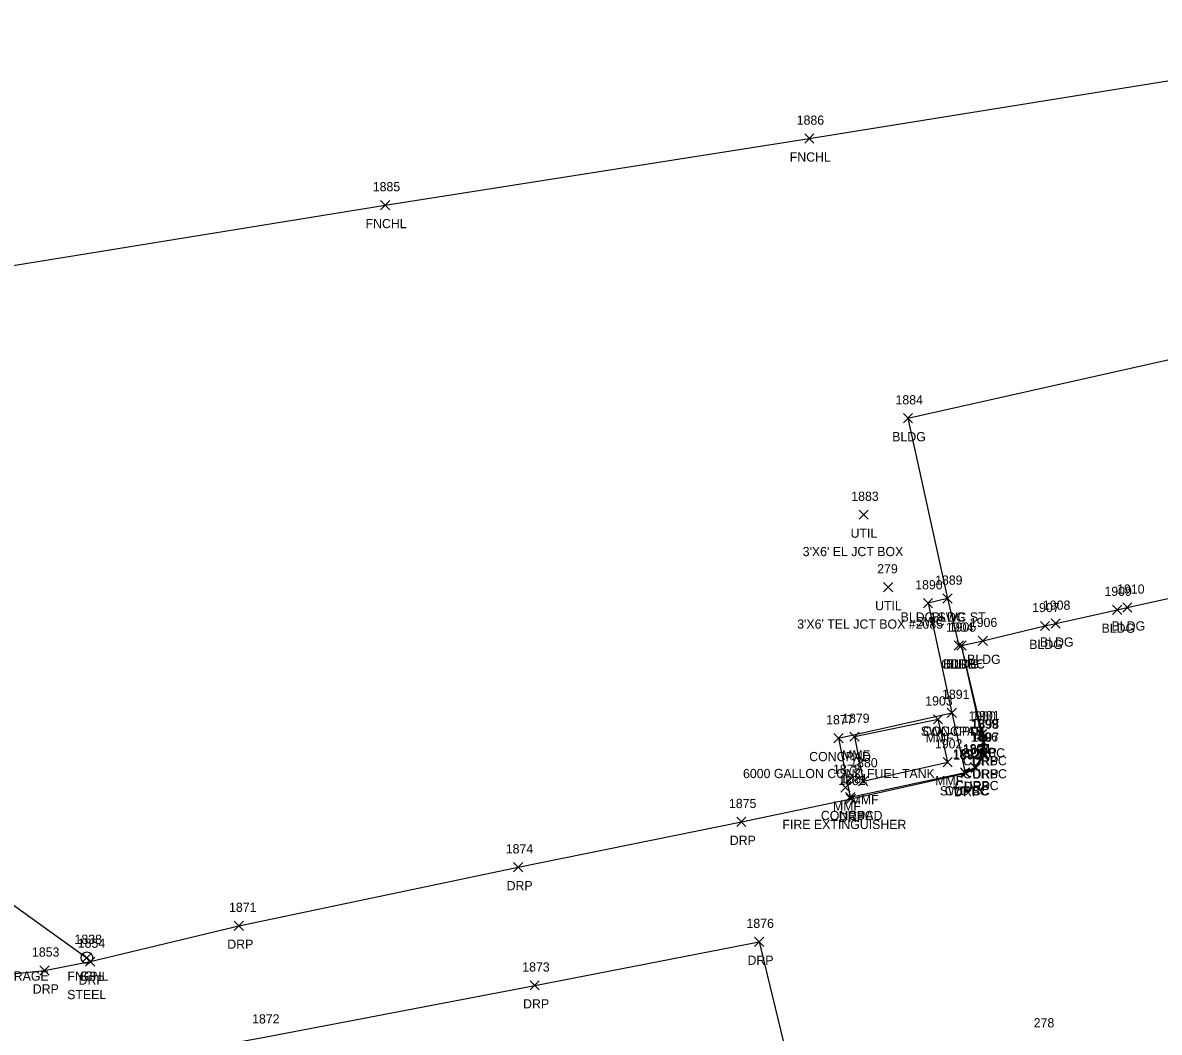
# Model space of a CAD drawing. Extents: x 1481523 to 1489083, y 884156 to 893756.
# Drawn here: x 1486651.1 to 1486897.7, y 888454.5 to 888673.5 of the extents above; entities that cross this region are included whole.
import ezdxf

# ---------------------------------------------------------------- set-up
doc = ezdxf.new("R2010")
doc.units = 0
for name, color, linetype in [('C_I', 7, 'Continuous'), ('L_A', 7, 'Continuous'), ('L_C', 7, 'Continuous'), ('L_I', 7, 'Continuous'), ('L_TIC', 7, 'Continuous'), ('LBC', 7, 'Continuous'), ('LDEFAULT', 7, 'Continuous'), ('LFNC', 7, 'Continuous'), ('LS', 7, 'Continuous'), ('R_A', 7, 'Continuous'), ('R_C', 7, 'Continuous'), ('R_I', 7, 'Continuous'), ('R_TIC', 7, 'Continuous'), ('RC', 7, 'Continuous'), ('RDP', 7, 'Continuous'), ('RGP', 7, 'Continuous'), ('RSW', 7, 'Continuous'), ('S_C', 7, 'Continuous'), ('U_A', 7, 'Continuous'), ('U_C', 7, 'Continuous'), ('U_I', 7, 'Continuous'), ('UDEFAULT', 7, 'Continuous')]:
    doc.layers.add(name, color=color, linetype=linetype)

msp = doc.modelspace()

# ---------------------------------------------------------------- linework, layer by layer
at = {"layer": 'L_TIC'}
for points in [[(1486820.77, 888647.41), (1486822.77, 888649.41)], [(1486822.77, 888647.41), (1486820.77, 888649.41)], [(1486728.72, 888632.96), (1486730.72, 888634.96)], [(1486730.72, 888632.96), (1486728.72, 888634.96)], [(1486842.17, 888586.71), (1486844.17, 888588.71)], [(1486844.17, 888586.71), (1486842.17, 888588.71)], [(1486842.17, 888586.71), (1486844.17, 888588.71)], [(1486844.17, 888586.71), (1486842.17, 888588.71)], [(1486850.76, 888547.58), (1486852.76, 888549.58)], [(1486852.76, 888547.58), (1486850.76, 888549.58)], [(1486887.59, 888545.15), (1486889.59, 888547.15)], [(1486889.59, 888545.15), (1486887.59, 888547.15)], [(1486889.77, 888545.64), (1486891.77, 888547.64)], [(1486891.77, 888545.64), (1486889.77, 888547.64)], [(1486874.23, 888542.15), (1486876.23, 888544.15)], [(1486876.23, 888542.15), (1486874.23, 888544.15)], [(1486871.9, 888541.63), (1486873.9, 888543.63)], [(1486873.9, 888541.63), (1486871.9, 888543.63)], [(1486853.19, 888537.38), (1486855.19, 888539.38)], [(1486855.19, 888537.38), (1486853.19, 888539.38)], [(1486853.8, 888537.4), (1486855.8, 888539.4)], [(1486855.8, 888537.4), (1486853.8, 888539.4)], [(1486858.42, 888538.39), (1486860.42, 888540.39)], [(1486860.42, 888538.39), (1486858.42, 888540.39)], [(1486851.69, 888522.8), (1486853.69, 888524.8)], [(1486853.69, 888522.8), (1486851.69, 888524.8)], [(1486848.7, 888521.37), (1486850.7, 888523.37)], [(1486850.7, 888521.37), (1486848.7, 888523.37)], [(1486848.7, 888521.37), (1486850.7, 888523.37)], [(1486850.7, 888521.37), (1486848.7, 888523.37)], [(1486827.1, 888517.29), (1486829.1, 888519.29)], [(1486829.1, 888517.29), (1486827.1, 888519.29)], [(1486827.1, 888517.29), (1486829.1, 888519.29)], [(1486829.1, 888517.29), (1486827.1, 888519.29)], [(1486830.59, 888517.61), (1486832.59, 888519.61)], [(1486832.59, 888517.61), (1486830.59, 888519.61)], [(1486830.59, 888517.61), (1486832.59, 888519.61)], [(1486832.59, 888517.61), (1486830.59, 888519.61)], [(1486850.79, 888512.06), (1486852.79, 888514.06)], [(1486852.79, 888512.06), (1486850.79, 888514.06)], [(1486832.43, 888507.95), (1486834.43, 888509.95)], [(1486834.43, 888507.95), (1486832.43, 888509.95)], [(1486828.6, 888506.56), (1486830.6, 888508.56)], [(1486830.6, 888506.56), (1486828.6, 888508.56)], [(1486829.63, 888504.5), (1486831.63, 888506.5)], [(1486831.63, 888504.5), (1486829.63, 888506.5)], [(1486664.01, 888469.64), (1486666.01, 888471.64)], [(1486666.01, 888469.64), (1486664.01, 888471.64)]]:
    msp.add_lwpolyline(points, dxfattribs=at)
at = {"layer": 'LBC'}
for points in [[(1486843.17, 888587.71), (1487025.25, 888628.62)], [(1486843.17, 888587.71), (1486851.76, 888548.58), (1486854.19, 888538.38), (1486854.8, 888538.4), (1486859.42, 888539.39), (1486872.9, 888542.63), (1486875.23, 888543.15), (1486888.59, 888546.15), (1486890.77, 888546.64), (1486904.16, 888549.62)]]:
    msp.add_lwpolyline(points, dxfattribs=at)
at = {"layer": 'LDEFAULT'}
for points in [[(1486831.59, 888518.61), (1486833.43, 888508.95), (1486851.79, 888513.06), (1486849.7, 888522.37)], [(1486831.59, 888518.61), (1486849.7, 888522.37)]]:
    msp.add_lwpolyline(points, dxfattribs=at)
at = {"layer": 'LFNC'}
for points in [[(1486611.93, 888614.86), (1486729.72, 888633.96), (1486821.77, 888648.41), (1486910.35, 888662.67), (1486965.56, 888671.42), (1487049.78, 888685.11)], [(1486611.93, 888614.86), (1486623.3, 888550.21), (1486633.47, 888493.25), (1486665.01, 888470.64)]]:
    msp.add_lwpolyline(points, dxfattribs=at)
at = {"layer": 'LS'}
for points in [[(1486828.1, 888518.29), (1486852.69, 888523.8)], [(1486828.1, 888518.29), (1486830.63, 888505.5)]]:
    msp.add_lwpolyline(points, dxfattribs=at)
at = {"layer": 'R_TIC'}
for points in [[(1486850.76, 888547.58), (1486852.76, 888549.58)], [(1486852.76, 888547.58), (1486850.76, 888549.58)], [(1486846.53, 888546.57), (1486848.53, 888548.57)], [(1486848.53, 888546.57), (1486846.53, 888548.57)], [(1486853.8, 888537.4), (1486855.8, 888539.4)], [(1486855.8, 888537.4), (1486853.8, 888539.4)], [(1486853.8, 888537.4), (1486855.8, 888539.4)], [(1486855.8, 888537.4), (1486853.8, 888539.4)], [(1486851.69, 888522.8), (1486853.69, 888524.8)], [(1486853.69, 888522.8), (1486851.69, 888524.8)], [(1486858.15, 888518.09), (1486860.15, 888520.09)], [(1486860.15, 888518.09), (1486858.15, 888520.09)], [(1486858.32, 888518.19), (1486860.32, 888520.19)], [(1486860.32, 888518.19), (1486858.32, 888520.19)], [(1486858.52, 888516.39), (1486860.52, 888518.39)], [(1486860.52, 888516.39), (1486858.52, 888518.39)], [(1486858.68, 888516.32), (1486860.68, 888518.32)], [(1486860.68, 888516.32), (1486858.68, 888518.32)], [(1486858.53, 888513.55), (1486860.53, 888515.55)], [(1486860.53, 888513.55), (1486858.53, 888515.55)], [(1486858.69, 888513.5), (1486860.69, 888515.5)], [(1486860.69, 888513.5), (1486858.69, 888515.5)], [(1486854.56, 888509.86), (1486856.56, 888511.86)], [(1486856.56, 888509.86), (1486854.56, 888511.86)], [(1486854.56, 888509.86), (1486856.56, 888511.86)], [(1486856.56, 888509.86), (1486854.56, 888511.86)], [(1486856.75, 888511), (1486858.75, 888513)], [(1486858.75, 888511), (1486856.75, 888513)], [(1486856.86, 888510.81), (1486858.86, 888512.81)], [(1486858.86, 888510.81), (1486856.86, 888512.81)], [(1486854.7, 888509.65), (1486856.7, 888511.65)], [(1486856.7, 888509.65), (1486854.7, 888511.65)], [(1486829.63, 888504.5), (1486831.63, 888506.5)], [(1486831.63, 888504.5), (1486829.63, 888506.5)], [(1486829.76, 888504.1), (1486831.76, 888506.1)], [(1486831.76, 888504.1), (1486829.76, 888506.1)], [(1486806.02, 888499.11), (1486808.02, 888501.11)], [(1486808.02, 888499.11), (1486806.02, 888501.11)], [(1486757.59, 888489.27), (1486759.59, 888491.27)], [(1486759.59, 888489.27), (1486757.59, 888491.27)], [(1486696.98, 888476.57), (1486698.98, 888478.57)], [(1486698.98, 888476.57), (1486696.98, 888478.57)], [(1486809.87, 888473.09), (1486811.87, 888475.09)], [(1486811.87, 888473.09), (1486809.87, 888475.09)], [(1486664.71, 888468.79), (1486666.71, 888470.79)], [(1486666.71, 888468.79), (1486664.71, 888470.79)], [(1486654.78, 888466.86), (1486656.78, 888468.86)], [(1486656.78, 888466.86), (1486654.78, 888468.86)], [(1486761.17, 888463.63), (1486763.17, 888465.63)], [(1486763.17, 888463.63), (1486761.17, 888465.63)]]:
    msp.add_lwpolyline(points, dxfattribs=at)
at = {"layer": 'RC'}
msp.add_lwpolyline([(1486830.63, 888505.5), (1486855.56, 888510.86), (1486857.75, 888512), (1486859.53, 888514.55), (1486859.52, 888517.39), (1486859.15, 888519.09), (1486854.8, 888538.4)], dxfattribs=at)
at = {"layer": 'RDP'}
for points in [[(1486614.23, 888481.5), (1486627.34, 888469.66), (1486637.68, 888466), (1486655.78, 888467.86), (1486665.71, 888469.79), (1486697.98, 888477.57), (1486758.59, 888490.27), (1486807.02, 888500.11), (1486830.76, 888505.1), (1486855.7, 888510.65), (1486857.86, 888511.81), (1486859.69, 888514.5), (1486859.68, 888517.32), (1486859.32, 888519.19), (1486854.8, 888538.4)], [(1486627.06, 888409.28), (1486634.2, 888424.78), (1486643.14, 888435.44), (1486660.74, 888444.3), (1486670.7, 888447.41), (1486703.54, 888453.36), (1486762.17, 888464.63), (1486810.87, 888474.09), (1486835.34, 888373.21), (1486845.25, 888329.26)]]:
    msp.add_lwpolyline(points, dxfattribs=at)
at = {"layer": 'RGP'}
msp.add_line((1486665.01, 888470.64), (1486665.01, 888470.64), dxfattribs=at)
for radius in [1.25, 0.0833]:
    msp.add_circle((1486665.01, 888470.64), radius, dxfattribs=at)
at = {"layer": 'RSW'}
msp.add_lwpolyline([(1486851.76, 888548.58), (1486847.53, 888547.57), (1486852.69, 888523.8), (1486855.56, 888510.86)], dxfattribs=at)
at = {"layer": 'UDEFAULT'}
for points in [[(1486832.56, 888565.78), (1486834.56, 888567.78)], [(1486834.56, 888565.78), (1486832.56, 888567.78)], [(1486837.87, 888550.04), (1486839.87, 888552.04)], [(1486839.87, 888550.04), (1486837.87, 888552.04)]]:
    msp.add_lwpolyline(points, dxfattribs=at)

# ---------------------------------------------------------------- texts
at = {"layer": 'C_I'}
msp.add_text('278', height=2, dxfattribs=at).set_placement((1486870.46, 888455.51))
at = {"layer": 'L_A'}
for s, p in [('FNCHL', (1486817.52, 888643.41)), ('FNCHL', (1486725.47, 888628.96)), ('BLDG', (1486839.76, 888582.71)), ('BLDG', (1486839.76, 888582.71)), ('BLDG', (1486848.35, 888543.58)), ('BLDG', (1486885.18, 888541.15)), ('BLDG', (1486887.36, 888541.64)), ('BLDG', (1486869.49, 888537.63)), ('BLDG', (1486871.82, 888538.15)), ('BLDG', (1486850.78, 888533.38)), ('BLDG', (1486851.39, 888533.4)), ('BLDG', (1486856.01, 888534.39)), ('CONCPAD', (1486846.34, 888518.8)), ('MMF', (1486846.98, 888517.37)), ('MMF', (1486846.98, 888517.37)), ('CONCPAD', (1486821.75, 888513.29)), ('CONCPAD', (1486821.75, 888513.29)), ('MMF', (1486828.87, 888513.61)), ('MMF', (1486828.87, 888513.61)), ('MMF', (1486849.08, 888508.06)), ('MMF', (1486826.89, 888502.56)), ('MMF', (1486830.72, 888503.95)), ('CONCPAD', (1486824.27, 888500.5)), ('FNCHL', (1486660.76, 888465.64))]:
    msp.add_text(s, height=2, dxfattribs=at).set_placement(p)
at = {"layer": 'L_C'}
for s, p in [('6000 GALLON CONC FUEL TANK', (1486807.38, 888509.61)), ('6000 GALLON CONC FUEL TANK', (1486807.38, 888509.61)), ('FIRE EXTINGUISHER', (1486815.93, 888498.56))]:
    msp.add_text(s, height=2, dxfattribs=at).set_placement(p)
at = {"layer": 'L_I'}
for s, p in [('1886', (1486819.03, 888651.41)), ('1885', (1486727.03, 888636.96)), ('1884', (1486840.47, 888590.71)), ('1884', (1486840.47, 888590.71)), ('1889', (1486849.06, 888551.58)), ('1910', (1486888.56, 888549.64)), ('1909', (1486885.81, 888549.15)), ('1907', (1486870.13, 888545.63)), ('1908', (1486872.46, 888546.15)), ('1906', (1486856.6, 888542.39)), ('1904', (1486851.42, 888541.38)), ('1905', (1486852.03, 888541.4)), ('1903', (1486846.93, 888525.37)), ('1903', (1486846.93, 888525.37)), ('1891', (1486850.57, 888526.8)), ('1877', (1486825.41, 888521.29)), ('1877', (1486825.41, 888521.29)), ('1879', (1486828.89, 888521.61)), ('1879', (1486828.89, 888521.61)), ('1902', (1486849.02, 888516.06)), ('1878', (1486826.91, 888510.56)), ('1880', (1486830.65, 888511.95)), ('1881', (1486828.5, 888508.5)), ('1838', (1486662.32, 888473.64))]:
    msp.add_text(s, height=2, dxfattribs=at).set_placement(p)
at = {"layer": 'R_A'}
for s, p in [('BLDG SWC ST', (1486841.58, 888543.58)), ('SWC', (1486844.89, 888542.57)), ('CURBC', (1486850.38, 888533.4)), ('DRP', (1486852.29, 888533.4)), ('SWC CPD1', (1486845.95, 888518.8)), ('CURBC', (1486854.73, 888514.09)), ('CURBC', (1486855.1, 888512.39)), ('DRP', (1486856.81, 888514.19)), ('DRP', (1486857.17, 888512.32)), ('CURBC', (1486855.12, 888509.55)), ('DRP', (1486857.18, 888509.5)), ('SWC CC', (1486850.09, 888505.86)), ('CURBC', (1486851.15, 888505.86)), ('DRP', (1486853.19, 888505.65)), ('CURBC', (1486853.33, 888507)), ('DRP', (1486855.35, 888506.81)), ('CURBC', (1486826.21, 888500.5)), ('DRP', (1486828.24, 888500.1)), ('DRP', (1486804.51, 888495.11)), ('DRP', (1486756.08, 888485.27)), ('DRP', (1486695.47, 888472.57)), ('DRP', (1486808.36, 888469.09)), ('GP', (1486663.44, 888465.64)), ('DRP', (1486663.2, 888464.79)), ('DRP', (1486653.26, 888462.86)), ('DRP', (1486759.66, 888459.63))]:
    msp.add_text(s, height=2, dxfattribs=at).set_placement(p)
at = {"layer": 'R_C'}
msp.add_text('STEEL', height=2, dxfattribs=at).set_placement((1486660.72, 888461.64))
at = {"layer": 'R_I'}
for s, p in [('1890', (1486844.75, 888550.57)), ('1889', (1486849.06, 888551.58)), ('1905', (1486852.03, 888541.4)), ('1905', (1486852.03, 888541.4)), ('1891', (1486850.57, 888526.8)), ('1900', (1486856.29, 888522.09)), ('1901', (1486857.12, 888522.19)), ('1899', (1486856.82, 888520.39)), ('1898', (1486856.99, 888520.32)), ('1896', (1486856.78, 888517.55)), ('1897', (1486857, 888517.5)), ('1895', (1486855.06, 888515)), ('1894', (1486855.16, 888514.81)), ('1892', (1486852.87, 888513.86)), ('1892', (1486852.87, 888513.86)), ('1893', (1486853, 888513.65)), ('1882', (1486828.06, 888508.1)), ('1881', (1486828.5, 888508.5)), ('1875', (1486804.33, 888503.11)), ('1874', (1486755.9, 888493.27)), ('1871', (1486695.85, 888480.57)), ('1876', (1486808.13, 888477.09)), ('1838', (1486662.32, 888473.64)), ('1854', (1486663.01, 888472.79)), ('1853', (1486653.08, 888470.86)), ('1873', (1486759.48, 888467.63)), ('1872', (1486700.85, 888456.36))]:
    msp.add_text(s, height=2, dxfattribs=at).set_placement(p)
at = {"layer": 'S_C'}
msp.add_text('DISTRICT 8 HIGHGATE GARAGE', height=2, dxfattribs=at).set_placement((1486615.25, 888465.65))
at = {"layer": 'U_A'}
for p in [(1486830.72, 888561.78), (1486836.04, 888546.04)]:
    msp.add_text('UTIL', height=2, dxfattribs=at).set_placement(p)
at = {"layer": 'U_C'}
for s, p in [("3'X6' EL JCT BOX", (1486820.33, 888557.78)), ("3'X6' TEL JCT BOX #2085", (1486819.14, 888542.04))]:
    msp.add_text(s, height=2, dxfattribs=at).set_placement(p)
at = {"layer": 'U_I'}
for s, p in [('1883', (1486830.87, 888569.78)), ('279', (1486836.5, 888554.04))]:
    msp.add_text(s, height=2, dxfattribs=at).set_placement(p)

doc.saveas('drawing.dxf')
